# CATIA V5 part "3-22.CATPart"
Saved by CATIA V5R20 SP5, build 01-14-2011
Part number: Part3
Material "Aluminium": density 2710 kg/m3, Young's modulus 7e+10 Pa, Poisson ratio 0.346, thermal expansion 2.36e-05 1/K
Bounding box of the stored display mesh (mm): x -25 to 25, y -25 to 25, z -60 to 50
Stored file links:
  E:\180511232\3-22.CATPart
  C:\Program Files\Dassault Systemes\B20\intel_a\startup\materials\Catalog.CATMaterial
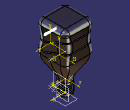
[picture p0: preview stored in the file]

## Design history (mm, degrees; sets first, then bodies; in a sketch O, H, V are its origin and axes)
Set1
  Sketch1 on xy-plane, origin (0, 0, 0), H (1, 0, 0), V (0, 1, 0)
    line L1 (25, 25) -> (25, -25)
    line L2 (25, -25) -> (-25, -25)
    line L3 (-25, -25) -> (-25, 25)
    line L4 (-25, 25) -> (25, 25)
    length L4 = 50
    length L1 = 50
    vertical: L1 V, L3 V
    horizontal: L2 H, L4 H
    equidistance: L1 L3 O, L2 L4 O
  Sketch2 on face of Pad1 from Sketch1.L3, origin (-25, 0, 0), H (0, -1, 0), V (0, 0, 1)
    spline S1 through (-42.1157, 18.4827) (-11.1794, 31.201) (8.2754, 22.6162) (38.5738, 31.201)
  Extrude1: Element1 Sketch2, Lim1 53, Lim2 53
  MultiSel1: CommonCtxFeats ({extract ExtractElem face of Pad1 from Sketch1.L3}; {extract ExtractElem face of Fillet1}; {extract ExtractElem face of Pad1 from Sketch1.L4}; {extract ExtractElem face of Fillet1}; {extract ExtractElem face of Pad1 from Sketch1.L1}; {extract ExtractElem face of Fillet1}; {extract ExtractElem face of Pad1 from Sketch1.L2}; {extract ExtractElem face of Fillet1})
  Sketch3 on face of Pad1 from Sketch1.L1, origin (25, 0, 0), H (0, 1, 0), V (0, 0, 1)
    spline S1 through (-35.6508, 14.5425) (-12.1043, 6.1379) (11.1515, 14.5425) (28.8841, 14.5425)
  Extrude2: Element1 Sketch3, Lim1 65, Lim2 65
  MultiSel2: CommonCtxFeats ({extract ExtractElem face of Pad1 from Sketch1.L1}; {extract ExtractElem face of Fillet1}; {extract ExtractElem face of Pad1 from Sketch1.L2}; {extract ExtractElem face of Fillet1}; {extract ExtractElem face of Pad1 from Sketch1.L3}; {extract ExtractElem face of Fillet1}; {extract ExtractElem face of Pad1 from Sketch1.L4}; {extract ExtractElem face of Fillet1})
  Join1: Elements ({intersect ToIntersect1 {extract ExtractElem face of Fillet1}, ToIntersect2 Extrude1}; {intersect ToIntersect1 {extract ExtractElem face of Pad1 from Sketch1.L4}, ToIntersect2 Extrude1}; {intersect ToIntersect1 {extract ExtractElem face of Fillet1}, ToIntersect2 Extrude1}; {intersect ToIntersect1 {extract ExtractElem face of Pad1 from Sketch1.L1}, ToIntersect2 Extrude1}; {intersect ToIntersect1 {extract ExtractElem face of Fillet1}, ToIntersect2 Extrude1}; {intersect ToIntersect1 {extract ExtractElem face of Pad1 from Sketch1.L2}, ToIntersect2 Extrude1}; {intersect ToIntersect1 {extract ExtractElem face of Fillet1}, ToIntersect2 Extrude1}; {intersect ToIntersect1 {extract ExtractElem face of Pad1 from Sketch1.L3}, ToIntersect2 Extrude1})
  Plane1: type OffsetPt, RefPlane face of Pad1 from Sketch1.L2, RefPoint vertex of MultiSel2
  Circle1: type CtrRad, Start 0, End 180, Center vertex of MultiSel2, Support Plane1, Radius 1, FirstDirection (-1, 0, 0)
  Plane2: type OffsetPt, RefPlane face of Pad1 from Sketch1.L2, RefPoint vertex [face of MultiSel1 | face of MultiSel1]
  Circle2: type CtrRad, Start 0, End 180, Center vertex [face of MultiSel1 | face of MultiSel1], Support Plane2, Radius 1, FirstDirection (-1, 0, 0)
Body1 (main body), material "Aluminium"
  Pad1: profile Sketch1, direction (0, 0, 1), length 50
  Fillet1: on edge [face of Pad1 from Sketch1.L4 | face of Pad1 from Sketch1.L1]; edge [face of Pad1 from Sketch1.L3 | face of Pad1 from Sketch1.L4]; edge [face of Pad1 from Sketch1.L1 | face of Pad1 from Sketch1.L2]; edge [face of Pad1 from Sketch1.L2 | face of Pad1 from Sketch1.L3]
  Fillet2: radius 8, on end face of Pad1
  Plane3: type Offset, RefPlane xy-plane, Offset 40, reversed
  Sketch4 on Plane3, origin (0, 0, -40), H (1, 0, 0), V (0, 1, 0)
  Sketch5 on Plane3, origin (0, 0, -40), H (1, 0, 0), V (0, 1, 0)
    circle A1 centre (0, 0) radius 10
    radius A1 = 10
  Sketch6 on start face of Pad1, origin (0, 0, 0), H (1, 0, 0), V (0, -1, 0)
    reference projected line E1 (-25, -25) -> (-25, 25) from edge [start face of Pad1 | face of Pad1 from Sketch1.L3]
    distance E1 O = 25
  Pad2: profile Sketch5, direction (0, 0, -1), length 20
  Sketch7 on start face of Pad1, origin (0, 0, 0), H (1, 0, 0), V (0, -1, 0)
    point P1 (25, 0)
    distance P1 O = 25
    coincidence: P1 H
  Sketch8 on Plane3, origin (0, 0, -40), H (1, 0, 0), V (0, 1, 0)
    point P1 (25, 0)
    distance P1 O = 25
    coincidence: P1 H
  Sketch9 on start face of Pad2, origin (0, 0, -40), H (1, 0, 0), V (0, 1, 0)
    point P1 (10, 0)
    distance P1 O = 10
    coincidence: P1 H
  Loft1: solid, Sections ({boundary Boundary {extract ExtractElem start face of Pad2}}; {boundary Boundary {extract ExtractElem start face of Pad1}}), StartFace start face of Pad2, EndFace start face of Pad1
  Slot1: profile Circle1, centre curve {join Elements ({intersect ToIntersect2 Extrude2}; {intersect ToIntersect2 Extrude2}; {intersect ToIntersect2 Extrude2}; {intersect ToIntersect2 Extrude2}; {intersect ToIntersect2 Extrude2}; {intersect ToIntersect2 Extrude2}; {intersect ToIntersect2 Extrude2}; {intersect ToIntersect2 Extrude2})}
  Slot2: profile Circle2, centre curve {join Elements ({intersect ToIntersect2 Extrude1}; {intersect ToIntersect2 Extrude1}; {intersect ToIntersect2 Extrude1}; {intersect ToIntersect2 Extrude1}; {intersect ToIntersect2 Extrude1}; {intersect ToIntersect2 Extrude1}; {intersect ToIntersect2 Extrude1}; {intersect ToIntersect2 Extrude1})}
  Shell1: ExtOffset 0, Face end face of Pad2, IntOffset 2
  Plane4: type OffsetPt, RefPlane yz-plane, RefPoint Sketch9
  Sketch10 on Plane4, origin (10, 0, 0), H (0, 1, 0), V (0, 0, 1)
    point P1 (0, -60)
    reference projected point E1 (0, -40) from Sketch9
    point P2 (0, -56.5)
    point P3 (0, -43.5)
    reference projected point E2 (0, -40) from Sketch9
    distance P1 E1 = 20
    distance P2 P1 = 3.5
    distance P3 E2 = 3.5
    coincidence: P1 V, P2 V, P3 V
  AxisLine1: Element face of Shell1
  Helix1: Direction AxisLine1, RefPoint Sketch10.P2, Pitch 1.5, Height 13, TaperAngle 0
  Loft2: solid, Sections ({boundary Boundary {extract ExtractElem start face of Pad2}}; {boundary Boundary {extract ExtractElem start face of Pad1}}), StartFace start face of Pad2, EndFace start face of Pad1
Body2
  Sketch11 on face of Pad1 from Sketch1.L2, origin (0, -25, 0), H (1, 0, 0), V (0, 0, 1)
    point P1 (-30.2053, 2.346)
    construction line L1 through (42.0975, -13.7551) direction (1, 0)
    construction line L2 through (86.6764, -29.8072) direction (0, 1)
    construction line L3 through (29.5005, 2.9963) direction (1, 0)
    construction line L4 through (29.5005, 2.9963) direction (0, 1)
    point P2 (11.3773, 4.4039)
    point P3 (-0.4552, 16.4417)
    polyline C1
    polyline C2
    polyline C3
    polyline C4
    polyline C5
    polyline C6
    polyline C7
    polyline C8
    polyline C9
    polyline C10
    polyline C11
    polyline C12
    polyline C13
  Point1: type OnCurve, Support Helix1, RefPoint vertex of Helix1, Length -10
  Line1: type Normal, RefPoint vertex of Helix1, RefSkin face of Pad2 from Sketch5.A1, Start 0, End 5
  Connect1: Curve1 Line1, Point1 vertex of Line1, Tension1 1.2, Curve2 Helix1, Point2 Point1, Tension2 1
  Point2: type OnCurve, Support Connect1, RefPoint Sketch10.P2, Length 10
  Point3: type OnCurve, Support Connect1, RefPoint Sketch10.P2, Length 10
  Line2: type Normal, RefPoint Sketch10.P2, RefSkin face of Pad2 from Sketch5.A1, Start 0, End 5
  Connect2: Curve1 Line2, Point1 vertex of Line2, Tension1 1, Curve2 Connect1, Point2 Point2, Tension2 1
  Plane5: type OffsetPt, RefPlane Plane4, RefPoint vertex of Connect2
  Sketch12 on Plane5, origin (5, 0, 0), H (0, 1, 0), V (0, 0, 1)
    circle A1 centre (0, -56.5418) radius 0.75
    point P1 (0, -56.5418)
    radius A1 = 0.75
    coincidence: P1 V
  Rib1: profile Sketch12, centre curve Connect2
  Plane6: type Offset, RefPlane end face of Pad2, Offset 10, reversed
  Sketch13 on end face of Pad2, origin (0, 0, -60), H (1, 0, 0), V (0, -1, 0)
    reference projected circle E1 centre (0, 0) radius 8 from edge [face of Shell1 | end face of Pad2]
    radius E1 = 8 (reference)
  Body3
    Sketch14 on Plane6, origin (0, 0, -70), H (1, 0, 0), V (0, 1, 0)
      circle A1 centre (0, 0) radius 8
      radius A1 = 8
    Pad3: profile Sketch14, direction (0, 0, 1), length 40
  Remove1: tool Body3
